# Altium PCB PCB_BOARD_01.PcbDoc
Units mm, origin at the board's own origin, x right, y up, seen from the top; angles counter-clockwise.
Board outline 110.24 x 84.07 mm, 2 copper layers (Top Layer, Bottom Layer); 80 components, 68 nets, 254 pads, 49 vias.
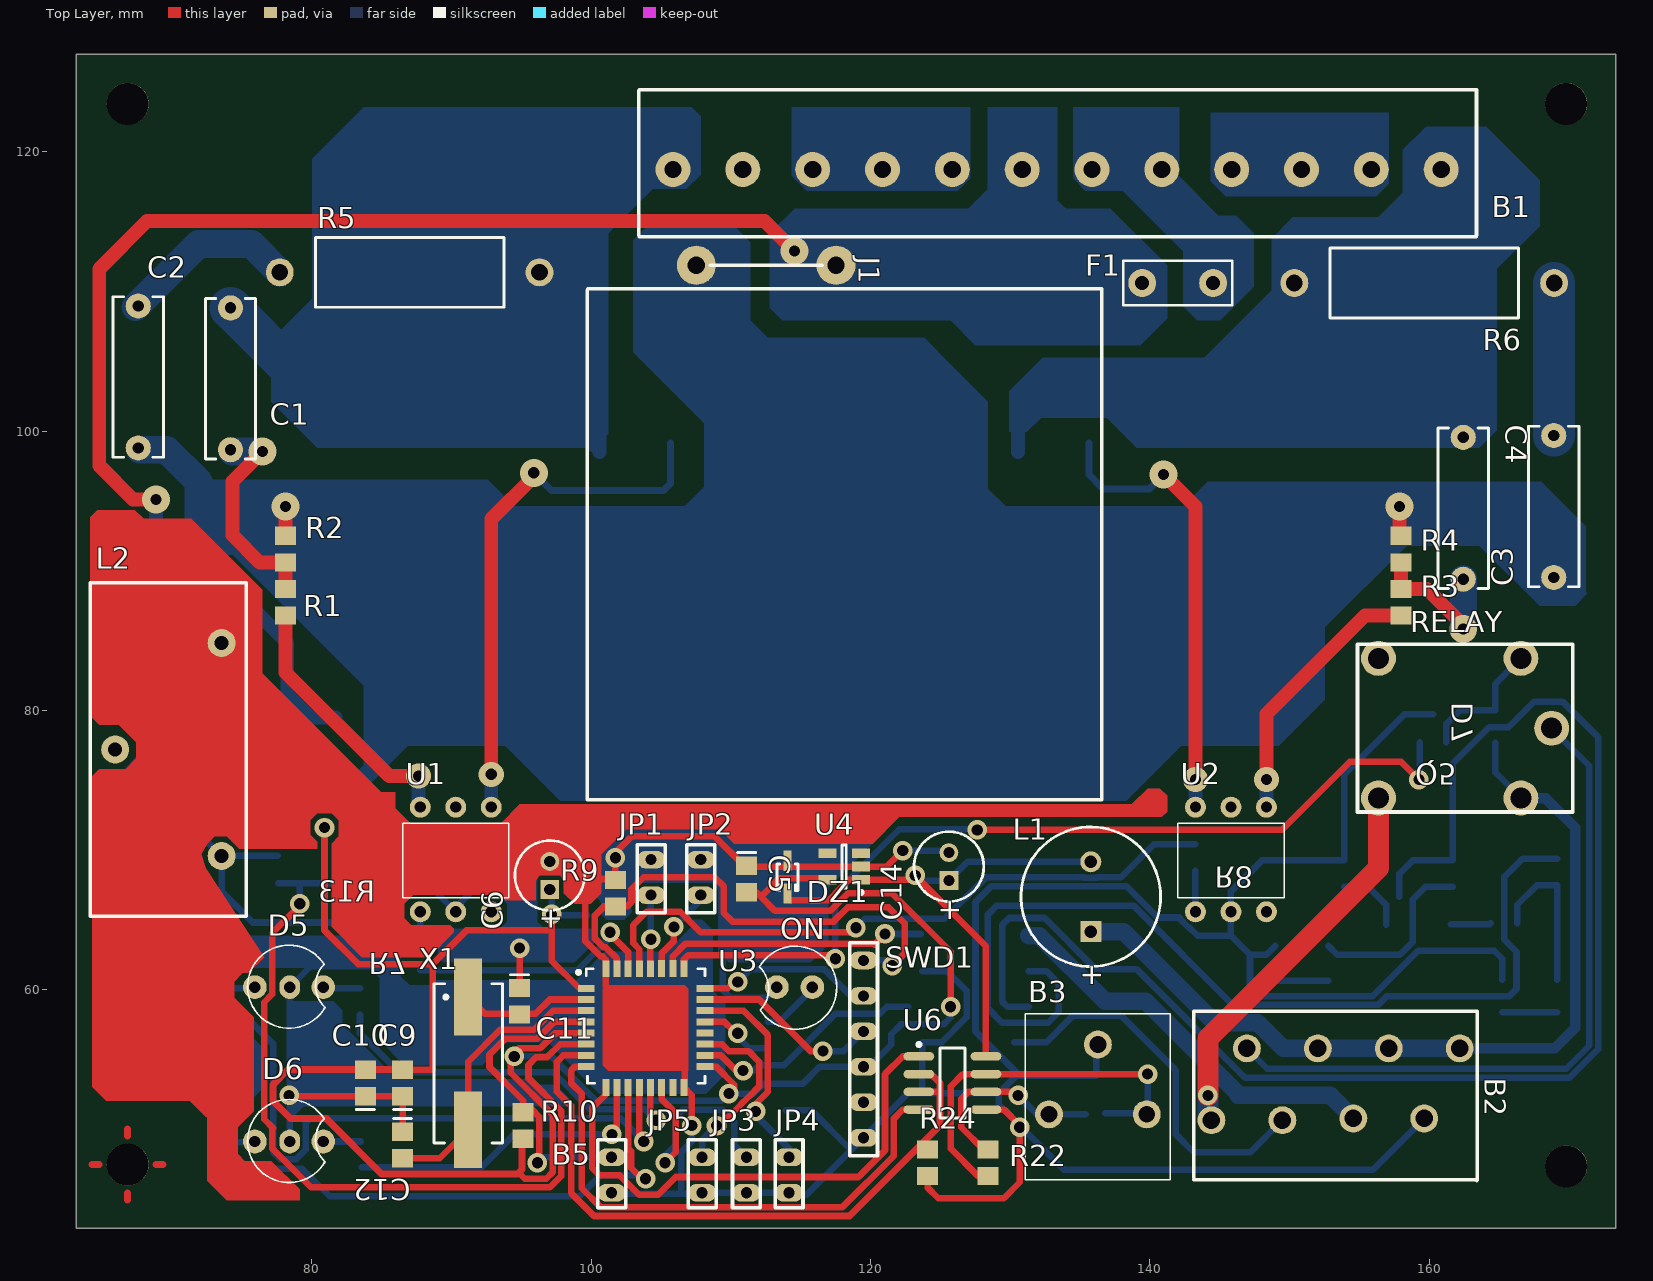
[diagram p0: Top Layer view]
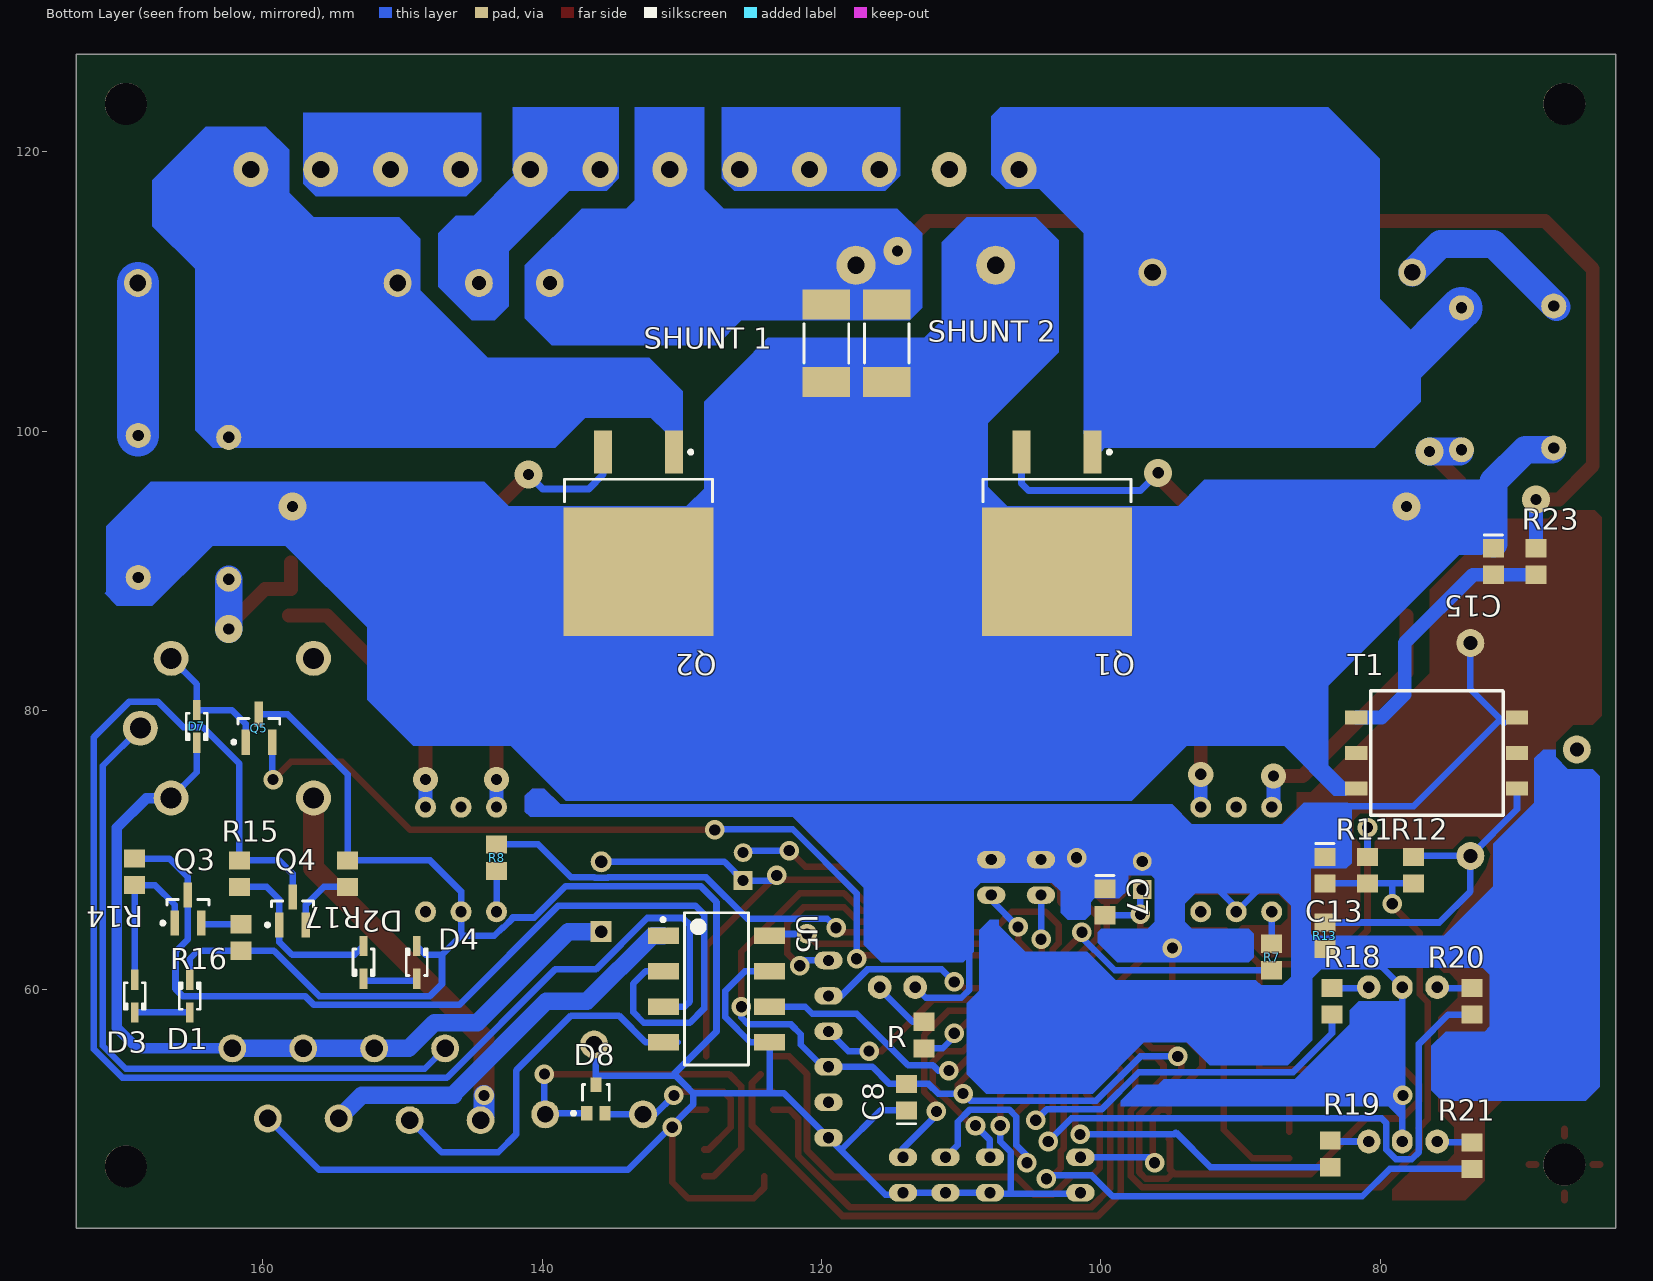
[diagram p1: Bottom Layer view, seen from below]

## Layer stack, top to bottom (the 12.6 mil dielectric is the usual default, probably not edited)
Top Solder: solder mask 0.0102, Solder Resist, Dk 3.5
Top Layer: signal copper 0.0356
Dielectric 1: dielectric 0.32, FR-4, Dk 4.8
Bottom Layer: signal copper 0.0356
Bottom Solder: solder mask 0.0102, Solder Resist, Dk 3.5

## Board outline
63.119,42.926 173.355,42.926 173.355,127 63.119,127

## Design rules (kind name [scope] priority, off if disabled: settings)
Clearance [All] p1: gap=0.152 ignorepadtopadclearanceinfootprint=FALSE except(0: Arc-Hole Track-Hole SMDPad-Hole THPad-Hole Via-Hole Fill-Hole Poly-Hole Region-Hole Text-Hole)
PolygonConnect [All] p1: connectstyle=Relief reliefconductorwidth=0.254 reliefentries=4 polygonreliefangle="90 Angle" airgapwidth=0.254
RoutingVias [All] p1: holewidth=0.711 width=1.27 viastyle="Through Hole" minholewidth=0.711 minwidth=1.27 maxholewidth=0.711 maxwidth=1.27
SolderMaskExpansion [All] p1: expansion=0.102
Width [All] p1: maxlimit=5 minlimit=0.254 preferedwidth=0.5
30 further rules are at their usual default settings.

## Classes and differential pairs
component class SPERIFERICOS: C5 C13 C14 D1 D2 D3 D4 D5 D6 D7 D8 DZ1 JP1 JP2 L1 L2 ON Q3 Q4 Q5 R R11 R12 R13 R14 R15 R16 R17 R18 R19 R20 R21 R22 R24 RELAY U4 U5 U6
component class MCU: B5 C6 C7 C8 C9 C10 C11 C12 JP3 JP4 JP5 R9 R10 SWD1 U3 X1
component class "CONTROL DE POTENCIA": B1 B2 B3 C1 C2 C3 C4 C15 F1 J1 Q1 Q2 R1 R2 R3 R4 R5 R6 R7 R8 R24 "SHUNT 1" "SHUNT 2" T1 U1 U2

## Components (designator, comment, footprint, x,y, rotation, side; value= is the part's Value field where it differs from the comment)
B1 "BLOCK TERMINAL 12P 16A" "BLOCK TERMINAL 12P 16A" 133.35,118.745 r0 top
B2 "BLOCK TERMINAL 12P 16A" "BORNERA 8P 2.5MM 2A" 153.289,53.467 r0 top
B3 "BORNERA 3P" BORNERA_ENCASTRE 136.271,53.594 r0 top
B5 "PINES_6" PINES_2_2.54 100.457,49.149 r270 top
C1 "47 nF  400V" VP60-3.6 74.168,103.759 r270 top
C2 "10nF" VP60-3.6 67.564,103.886 r270 top
C3 "10nF" VP60-3.6 168.91,94.615 r270 top
C4 "47 nF  400V" VP60-3.6 162.433,94.488 r270 top
C5 "0" 0805 111.125,67.945 r270 top
C6 "100uf 16V" CAPPR2-5X11 97.028,68.199 r90 top
C7 "10 nF" 0805 99.695,66.294 r270 bottom
C8 "1000 nF" 0805 113.919,52.324 r90 bottom
C9 "100 nF" 0805 86.487,53.34 r90 top
C10 "100nF" 0805 83.82,53.34 r90 top
C11 "10 pF" 0805 94.869,59.182 r270 top
C12 "10 pF" 0805 86.487,48.895 r270 top
C13 "10 nF" 0805 83.947,68.58 r270 bottom
C14 "100uf 16V" CAPPR2-5X11 125.603,68.834 r90 top
C15 "10 nF" 0805 71.882,90.678 r270 bottom
D1 "1N4448" SOD-323 169.164,59.563 r270 bottom
D2 "1N4448" SOD-323 152.781,61.976 r270 bottom
D3 "1N4448" SOD-323 165.227,59.563 r90 bottom
D4 "1N4448" SOD-323 148.971,61.976 r90 bottom
D5 "B1" LED_BICOLOR 78.359,60.198 r0 top
D6 "B2" LED_BICOLOR 78.359,49.149 r0 top
D7 "1N4448" SOD-323 164.719,78.867 r270 bottom
D8 "CDSOT23-SM712" SOT-323 136.144,52.197 r180 bottom
DZ1 "MM5Z5V1T1G" SOD323 114.046,68.072 r270 top
F1 "FUSE" VP45-3.2 141.986,110.617 r180 top
J1 "JUMPER" "JUMPER 10MM" 112.522,111.887 r0 top
JP1 "PINES_6" PINES_2_2.54 105.283,65.659 r90 top
JP2 "PINES_6" PINES_2_2.54 108.839,65.659 r90 top
JP3 "PINES_6" PINES_2_2.54 110.109,49.149 r270 top
JP4 "PINES_6" PINES_2_2.54 113.157,49.149 r270 top
JP5 "PINES_6" PINES_2_2.54 106.934,49.149 r270 top
L1 "1mH 200mW" CAPPR5-10X12.5 135.763,66.675 r90 top
L2 "INDUCTOR" AC1015 69.723,77.216 r270 top
ON "ON" LED 114.554,60.198 r180 top (schematic designator D)
Q1 "T2050H" TO254P1280-3_4M 103.124,92.71 r270 bottom
Q2 "T2050H" TO254P1280-3_4M 133.096,92.71 r270 bottom
Q3 "BC817" SOT23-3M 165.354,65.786 r90 bottom
Q4 "BC817" SOT23-3M 157.861,65.659 r90 bottom
Q5 "BSS138" SOT23-3M 160.274,78.74 r90 bottom
R "56 ohm" ERA-0805 112.649,56.769 r90 bottom
R1 "390" ERA-0805 78.105,87.757 r270 top (schematic designator R3)
R2 "470" ERA-0805 78.105,91.567 r270 top (schematic designator R1)
R3 "390" ERA-0805 157.988,87.757 r270 top (schematic designator R4)
R4 "470" ERA-0805 157.988,91.567 r270 top (schematic designator R2)
R5 "39 2W" R12x4 86.995,111.379 r180 top
R6 "39 2W" R12x4 159.639,110.617 r0 top
R7 "220" ERA-0805 87.757,62.357 r90 bottom
R8 "220" ERA-0805 143.256,69.469 r270 bottom
R9 "100K" ERA-0805 101.727,66.929 r270 top
R10 "10K" ERA-0805 95.123,50.292 r270 top
R11 "330" ERA-0805 80.899,68.58 r90 bottom
R12 "220" ERA-0805 77.597,68.58 r270 bottom
R13 "100" ERA-0805 83.947,63.881 r90 bottom
R14 "520" ERA-0805 169.164,68.453 r270 bottom
R15 "520" ERA-0805 161.671,68.326 r270 bottom
R16 "56 ohm" ERA-0805 161.544,63.754 r270 bottom
R17 "56 ohm" ERA-0805 153.924,68.326 r90 bottom
R18 "56 ohm" ERA-0805 83.439,59.182 r90 bottom
R19 "56 ohm" ERA-0805 83.566,48.26 r90 bottom
R20 "56 ohm" ERA-0805 73.406,59.182 r90 bottom
R21 "56 ohm" ERA-0805 73.406,48.133 r90 bottom
R22 "100" ERA-0805 128.397,47.625 r90 top
R23 "10" ERA-0805 68.834,90.678 r90 bottom
R24 "1K" ERA-0805 124.079,47.625 r90 top (schematic designator R23)
RELAY "RELE SIMPLE INVERSOR" "RELAY NT78" 162.56,78.74 r180 top
"SHUNT 1" "0,2 ohm" M1WS-2512 119.634,106.299 r270 bottom
"SHUNT 2" "0,2" M1WS-2512 115.316,106.299 r270 bottom
SWD1 "PINES_6" PINES_6_2.54 118.491,63.246 r270 top
T1 "TRANSFORMADOR" "TRANSFORMADOR TRANSMISION DE DATOS" 75.946,76.962 r0 bottom
U1 "MOC3041" DIP_6 90.297,69.342 r0 top
U2 "MOC3021" DIP_6 145.796,69.342 r0 top
U3 "STMF030K6T6" LQFP_32 103.886,57.277 r0 top
U4 "MIC5504-3.3YM5-TR" SOT23-5AM 118.11,68.834 r180 top
U5 "MCT6" S-DIP-8 127.508,60.071 r270 bottom
U6 "THVD1500" D008_N 125.857,53.34 r0 top
X1 "8Mhz Cristal" HC49/4H_SMX 91.186,54.737 r270 top

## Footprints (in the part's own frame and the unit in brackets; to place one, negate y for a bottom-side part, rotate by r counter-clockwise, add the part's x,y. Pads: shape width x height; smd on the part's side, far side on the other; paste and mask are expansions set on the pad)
0805 [mm] "Chip Capacitor; Body 2.0 x 1.2 mm (LxW typ)"
  rect 1.3x1.5 smd: 1(-0.95,0) 2(0.95,0)
  silkscreen extent -1.9,-0.65 -1.9,0.65
AC1015 [mm] "Transformador de corriente no invasivo"
  round 2 hole 1: 1(-7.62,3.81) 2(7.62,3.81) 3(0,-3.81)
  silkscreen extent -11.94,-5.59 11.94,5.59
"BLOCK TERMINAL 12P 16A" [mm] "8 pines, paso 5 mm, 16A 400V"
  round 2.5 hole 1.25: 1(-27.5,0) 2(-22.5,0) 3(-17.5,0) 4(-12.5,0) 5(-7.5,0) 6(-2.5,0) 7(2.5,0) 8(7.5,0) 9(12.5,0) 10(17.5,0) 11(22.5,0) 12(27.5,0)
  silkscreen extent -29.96,-4.83 30.03,5.7
"BORNERA 8P 2.5MM 2A" [mm]
  round 2 hole 1.25: 1(-8.89,-2.794) 2(-6.35,2.349) 3(-3.81,-2.794) 4(-1.27,2.349) 5(1.27,-2.667) 6(3.81,2.349) 7(6.35,-2.667) 8(8.89,2.349)
  silkscreen extent -10.16,-7.11 10.16,5.02
BORNERA_ENCASTRE [mm] "PASO 3.5MM 3 POLOS"
  round 2 hole 1.2: 1(-3.5,-2.5) 2(0,2.5) 3(3.5,-2.5)
  silkscreen extent -5.2,-7.2 5.2,4.7
CAPPR2-5X11 [mm] "Capacitor, Electrolytic, Radial; Body 5 x 11 mm (Dia.xH typ); Pin Spacing 2 mm (typ)"
  rect 1.35x1.35 hole 0.8: 1(-1,0)
  round 1.35 hole 0.8: 2(1,0)
  silkscreen extent -2.5,-2.5 2.5,2.5
CAPPR5-10X12.5 [mm] "Capacitor, Electrolytic, Radial; Body 10 x 12.5 mm (Dia.xH typ); Pin Spacing 5 mm (typ)"
  rect 1.5x1.5 hole 0.9: 1(-2.5,0)
  round 1.5 hole 0.9: 2(2.5,0)
  silkscreen extent -5,-5 5,5
D008_N [mm] "SOIC, 8-Leads, Body 4.9x3.9mm, Pitch 1.27mm, IPC Medium Density"
  oval 2.2x0.6 smd: 1(-2.4,1.905) 2(-2.4,0.635) 3(-2.4,-0.635) 4(-2.4,-1.905) 5(2.4,-1.905) 6(2.4,-0.635) 7(2.4,0.635) 8(2.4,1.905)
  silkscreen extent -2.52,-2.5 0.9,2.88, body extent -1.95,-2.45 1.95,2.45, height 1.75
DIP_6 [mm]
  round 1.5 hole 0.8: 1(-2.54,-3.746) 2(0,-3.746) 3(2.54,-3.746) 4(2.54,3.746) 5(0,3.746) 6(-2.54,3.746)
  silkscreen extent -3.81,-2.73 3.81,2.6
ERA-0805 [mm] "Chip Resistor; Body 2 x 1.3 mm (LxW typ)"
  rect 1.3x1.5 smd: 1(-0.95,0) 2(0.95,0)
HC49/4H_SMX [mm] "Surface Mount Quartz Crystal; Body 13.4 (inc. leads) x 4.9 mm (LxW max)"
  rect 5.5x2 smd: 1(-4.75,0) 2(4.75,0)
  silkscreen extent -5.7,-2.45 5.7,2.45
"JUMPER 10MM" [mm] "JUMPER 10MM"
  round 2.8 hole 1.25: 1(-5,0) 2(5,0)
  silkscreen extent -4,0 4,0
LED [mm] "LED 5MM"
  round 1.7 hole 0.8: 1(-1.27,0) 2(1.27,0)
  silkscreen extent -3.02,-2.93 2.52,3.01
LED_BICOLOR [mm] "LTL.30EFJ"
  round 1.7 hole 0.8: 1(2.45,0) 3(-2.45,0)
  oval 1.5x1.7 hole 0.8: 2(0.05,0)
  silkscreen extent -2.97,-2.93 2.57,3.01
LQFP_32 [mm] "LQFP, 32-Leads, Body 7x7mm, Pitch 0.8mm"
  rect 1.2x0.5 smd: 1(-4.25,2.838) 2(-4.25,2.038) 3(-4.25,1.238) 4(-4.25,0.438) 5(-4.25,-0.362) 6(-4.25,-1.162) 7(-4.25,-1.962) 8(-4.25,-2.762) 17(4.25,-2.762) 18(4.25,-1.962) 19(4.25,-1.162) 20(4.25,-0.362) 21(4.25,0.438) 22(4.25,1.238) 23(4.25,2.038) 24(4.25,2.838)
  rect 0.5x1.2 smd: 9(-2.85,-4.262) 10(-2.05,-4.262) 11(-1.25,-4.262) 12(-0.45,-4.262) 13(0.35,-4.262) 14(1.15,-4.262) 15(1.95,-4.262) 16(2.75,-4.262) 25(2.75,4.238) 26(1.95,4.263) 27(1.15,4.263) 28(0.35,4.238) 29(-0.45,4.238) 30(-1.25,4.238) 31(-2.05,4.238) 32(-2.85,4.238)
  silkscreen extent -4.92,-3.96 4.25,4.24, body extent -4.12,-3.94 4.03,4.21, height 1
M1WS-2512 [mm] "Chip Resistor; Body 6.4 x 3.2 mm (LxW typ)"
  rect 2.15x3.4 smd: 1(-2.775,0) 2(2.775,0)
  silkscreen extent -1.4,-1.6 1.4,1.6
PINES_2_2.54 [mm]
  oval 1.27x2.032 hole 0.8: 1(1.13,1) 2(3.67,1)
  silkscreen extent -0.12,0 4.75,2
PINES_6_2.54 [mm]
  oval 1.27x2.032 hole 0.8: 1(1.13,1) 2(3.67,1) 3(6.21,1) 4(8.75,1) 5(11.29,1) 6(13.83,1)
  silkscreen extent -0.12,0 15.13,2
R12x4 [mm] "Resistor, Axial; Body 13.5 x 5 mm (LxDia. max), Lead Dia. 0.85 mm (max)"
  round 2 hole 1.2: 1(-9.3,0) 2(9.3,0)
  silkscreen extent -6.75,-2.5 6.75,2.5
"RELAY NT78" [mm] "RELE SIMPLE INVERSOR"
  round 2.5 hole 1.5: 1(-4,5) 2(-4,-5) 3(-6.2,0) 4(6.2,5) 5(6.2,-5)
  silkscreen extent -7.7,-6 7.7,6
S-DIP-8 [mm] "DIP; 8 Trim Leads; Row Spacing 7.62 mm; Pitch 2.54 mm"
  rect 1.2x2.2 smd: 1(-3.81,-3.8) 2(-1.27,-3.8) 3(1.27,-3.8) 4(3.81,-3.8) 5(3.81,3.8) 6(1.27,3.8) 7(-1.27,3.8) 8(-3.81,3.8)
  silkscreen extent -5.45,-3.95 5.45,2.3
SOD323 [mm] "SOD-323/SC-76; 2 Leads; Body 1.7 x 1.3 mm, (LxW)"
  rect 1.45x0.55 smd: 1(1.175,0) 2(-1.175,0)
  silkscreen extent -0.95,-0.75 0.95,0.75
SOD-323 [mm] "SOD-323/SC-76; 2 Leads; Body 1.7 x 1.3 mm, (LxW)"
  rect 1.45x0.55 smd: 1(1.175,0) 2(-1.175,0)
  silkscreen extent -0.95,-0.75 0.95,0.75
SOT23-3M [mm] "SOT23, 3-Leads, Body 2.9x1.3mm, Pitch 0.95mm, Lead Span 2.5mm, IPC Low Density"
  rect 1.8x0.6 smd: 1(-1,0.95) 2(-1,-0.95) 3(1,0)
  silkscreen extent -1.12,-1.5 0.7,1.93, body extent -0.7,-1.5 0.7,1.5, height 1.1
SOT23-5AM [mm] "SOT23, 5-Leads, Body 2.9x1.7mm, Pitch 0.95mm, Lead Span 2.8mm, IPC Low Density"
  rect 1.3x0.7 smd: 1(-1.2,0.95) 2(-1.2,0) 3(-1.2,-0.95) 4(1.2,-0.95) 5(1.2,0.95)
  silkscreen extent -1.33,-1.55 0.15,1.97, body extent -0.9,-1.55 0.9,1.55, height 1.45
SOT-323 [mm] "SOT-323/SC-70; 3 Leads; Body 2.2 x 2.2 mm, inc. leads (LxW max)"
  rect 0.8x1.05 smd: 1(-0.65,-1.025) 2(0.65,-1.025) 3(0,1.025)
  silkscreen extent -1.73,-1.15 0.95,1.03
TO254P1280-3_4M [mm] "TO, 4-Leads, Body 9.6x10.2mm, Pitch 2.54mm, Lead Span 12.8mm, IPC Low Density"
  rect 3.1x1.3 smd: 1(-5.8,2.54) 3(-5.8,-2.54)
  rect 9.2x10.75 smd: 4(2.75,0)
  silkscreen extent -5.92,-5.3 -2.25,5.3, body extent -4.35,-5.3 5.25,5.3, height 5.1
"TRANSFORMADOR TRANSMISION DE DATOS" [mm] "TRANFORMADOR DE AUDIO PARA TRANSMISION DE DATOS SMD"
  rect 1.6x1 smd: 1(-5.75,2.54) 2(-5.75,0) 3(-5.75,-2.54) 4(5.75,-2.54) 5(5.75,0) 6(5.75,2.54)
  silkscreen extent -4.76,-4.47 4.73,4.46
VP45-3.2 [mm] "Capacitor, Ceramic, Thru-Hole, Dipped Radial; Body 7.8 x 3.2 mm (WxT) Pin Spacing 5.08 mm (typ)"
  round 2 hole 1: 1(-2.54,0) 2(2.54,0)
  silkscreen extent -3.9,-1.6 3.9,1.6
VP60-3.6 [mm] "Capacitor, Ceramic, Thru-Hole, Dipped Radial; Body 11.5 x 3.6 mm (WxT) Pin Spacing 10.16 mm (typ)"
  round 1.8 hole 0.8: 1(-5.08,0) 2(5.08,0)
  silkscreen extent -5.75,-1.8 5.75,1.8

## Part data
B5 JP1 JP2 JP3 JP4 JP5 SWD1: "6 Pines - 2.54 mm"
C1 C4 C5 C7 C8 C9 C10 C11 C12 C13 C15: library part C0805, "Ceramic Chip Capacitor - Standard"
C2 C3: library part VP52BA102GC, "Dipped Radial Multilayer Ceramic Capacitor COG (NPO): 1000pF, 200V"
C6 C14: library part 94SL106X0016CBP, "CAPACITOR ELECTROLITICO RADIAL"
D1 D2 D3 D4 D7: library part 1N4044, "275 Amp Avg Power Silicon Rectifier Diode"
D5 D6: library part LED_BICOLOR_CC, "Led bicolor catodo comun"
D8: library part BAR64-05W, "PIN Diode for RF switches (High Isolation)"
DZ1: library part 1N968B, "Half Watt Zener"
F1: "Fusible 0697H9200-02 - 20A Slow"
J1: "PUENTE"
L1: library part INDUCTOR, "INDUCTOR SMD"
L2: "INDUCTOR SMD"
ON: library part LED, "LED"
Q1 Q2: library part Q8025R5, "Triac (25.0 Amps)"
Q3 Q4: library part BC817-16LT1, "General Purpose Transistor NPN Silicon"
Q5: library part IRF5NJZ48, "HEXFET Power MOSFET"
R R1 R2 R3 R4 R7 R8 R9 R10 R11 R12 R13 R14 R15 R16 R17 R18 R19 R20 R21 R22 R23 R24 "SHUNT 1" "SHUNT 2": library part ERAS, "Metal Film Thermosensitive Chip Resistor, 0.56 Ohm to 10k Ohm Range, 5% Tolerance, 0805 Size, 0.1 W"
R5 R6: library part ERG2, "Metal Oxide Film Resistor, 0.1 Ohm to 100k Ohm Range, 2% and 5% Tolerance, 2 W"
U1: library part MOC3021, "OPTOACOPLADOR"
U2: "OPTOACOPLADOR"
U4: library part MC33275ST-5.0T3, "Low Dropout 300mA Voltage Regulator"
U5: library part PC827, "OPTOACOPLADOR"
U6: library part TL3695D, "Differential Bus Transceiver"
X1: library part HC49/4H_SMX, "Surface Mount Quartz Crystal"

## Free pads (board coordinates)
  round 3 hole 3: 2(66.802,47.498) 2(66.802,123.444) 2(169.799,47.371) 2(169.799,123.444)

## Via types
v1: diameter 1.4, hole 0.8, Top Layer to Bottom Layer, 37 vias
v2: diameter 2, hole 0.8, Top Layer to Bottom Layer, 8 vias
v3: diameter 1.8, hole 0.8, Top Layer to Bottom Layer, 4 vias

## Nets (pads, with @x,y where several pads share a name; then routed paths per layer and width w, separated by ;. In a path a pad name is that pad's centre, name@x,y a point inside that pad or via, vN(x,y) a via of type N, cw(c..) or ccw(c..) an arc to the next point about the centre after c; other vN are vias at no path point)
3V3: C5.2 C6.1 C7.2 C8.2 C9.2 C10.2 R10.2 R11.2 SWD1.4 U3.1 U3.5 U3.17 U4.5 | length 165.8
  Top Layer w0.47: v1(80.899,71.628) 80.899,64.262 83.312,61.849 88.646,61.849 ; C9.2 88.646,54.29 88.646,61.849 ; 94.982,46.736 95.236,46.482 96.774,46.482 97.226,46.934 97.226,51.086 94.234,54.079 94.234,55.245 94.801,55.812 96.325,55.812 97.428,56.915 U3.5 ; 97.028,64.262 91.059,64.262 88.646,61.849 ; 97.155,62.357 97.155,62.098 ; v1(97.155,65.405) 97.155,62.098 ; U3.1 99.138,60.115 97.155,62.098 ; U3.17 108.934,54.515 110.236,53.213 v1@110.236,52.705 ; C5.2 111.821,66.995 112.141,66.675 ; U4.5 116.91,68.009 113.475,68.009 112.141,66.675 ; v1(125.73,58.801) 125.73,62.738 121.539,66.929 118.383,66.929 117.113,65.659 113.157,65.659 112.141,66.675
  Top Layer w0.5: C9.2 C10.2 78.293,54.29 77.216,53.213 77.216,52.035 78.451,50.8 81.026,50.8 84.991,46.835 94.714,46.835 95.037,47.158 95.037,49.256 R10.2
  Bottom Layer w0.47: R11.2 v1(80.899,71.628) ; v1(94.488,55.245) 97.155,55.245 100.33,52.07 109.347,52.07 v1(109.855,52.578) 111.633,52.578 112.329,53.274 C8.2 115.123,53.274 116.345,54.496 SWD1.4 119.901,54.496 121.475,56.07 121.475,56.832 122.174,57.531 125.222,57.531 125.73,58.039 v1(125.73,58.801) ; v1(97.155,65.405) C6.1@97.155,67.072 ; v1@97.348,65.344 C7.2
5V: B2.4 B2.6 B2.8 D7.1 L1.1 RELAY.1 | length 62.3
  Bottom Layer w0.47: D7.1 164.719,75.581 RELAY.1
  Bottom Layer w0.75: B2.8 168.974,55.816 170.447,57.29 170.447,71.615 168.322,73.74 RELAY.1
  Bottom Layer w1.25: L1.1@136.017,64.175 138.136,64.175 144.653,57.658 147.701,57.658 149.542,55.816 B2.4 B2.6 B2.8
5VCC: C14.1 DZ1.1 L1.2 U4.1 U6.8 | length 38.3
  Top Layer w0.47: DZ1.1@114.046,66.421 115.715,66.421 115.763,66.373 116.279,66.373 116.327,66.421 116.995,66.421 117.947,67.374 117.947,67.393 118.439,67.884 U4.1 122.875,67.884 v1(123.19,68.199) 128.257,63.132 U6.8
  Bottom Layer w0.47: v1(123.19,68.199) 123.555,67.834 C14.1 126.944,69.175 L1.2
GND: B2.7 B3.2 B5.2 C5.1 C6.2 C7.1 C8.1 C9.1 C10.1 C11.1 C12.1 C13.1 C14.2 D3.1 D4.1 D5.2 D6.2 D8.3 DZ1.2 JP1.2 JP2.2 JP3.2 JP4.2 JP5.2 L2.1 ON.2 Q5.3 R9.1 R13.1 R16.2 R17.2 R24.1 SWD1.6 T1.3 U1.2 U2.2 U3.16 U3.32 U4.2 U5.5 U5.7 U6.5 | length 365.9
  Top Layer w0.47: v1(78.359,52.451) 78.42,52.39 C10.1 C9.1 C12.1 ; C11.1 v1(94.869,62.992) ; R9.1@101.727,67.818 R9.1 R9.1@101.727,67.945 ; R9.1@102.108,67.945 R9.1@101.727,67.945 ; U3.16 107.188,52.463 v1(107.188,50.292) ; U3.16@106.68,53.059 106.68,54.61 101.036,60.254 U3.32 101.036,62.159 100.77,62.425 100.638,62.425 99.568,63.495 99.568,66.802 100.711,67.945 R9.1@101.727,67.945 ; v1@122.555,70.231 v1(122.301,69.977) 121.158,68.834 U4.2 110.998,68.834 108.839,70.993 102.87,70.993 101.727,69.85 v1(101.727,69.469) R9.1@101.727,67.945 ; R24.1 124.079,45.847 124.841,45.085 129.54,45.085 130.683,46.228 v1(130.683,50.165) 130.683,50.292 129.54,51.435 U6.5
  Bottom Layer w0.47: 71.12,79.121 71.374,79.375 ; L2.1 73.533,81.534 71.374,79.375 ; D6.2@78.359,49.353 D6.2@78.409,49.303 ; D6.2 D6.2@78.409,49.303 ; D6.2@78.486,49.226 D6.2@78.409,49.303 ; v1(94.869,62.992) 94.869,69.072 94.996,69.199 ; C7.1 99.695,68.199 ; B5.2 101.541,45.395 107.85,45.395 JP5.2 JP3.2 JP4.2@114.03,45.479 ; 106.426,45.479 106.426,48.387 107.188,49.149 v1(107.188,50.292) ; JP2.2@107.699,69.469 v1(101.727,69.469) 100.711,69.469 99.695,68.453 99.695,68.199 ; JP2.2 108.09,69.329 109.41,68.008 109.403,68.001 109.403,60.015 109.982,59.436 112.522,59.436 ON.2 ; C8.1 115.758,51.374 118.54,48.592 ; JP4.2@114.157,45.352 115.427,45.352 SWD1.6 122.692,52.617 129.159,52.617 ; v1(122.301,69.977) 125.46,69.977 C14.2 ; 123.708,52.627 U5.5 125.095,56.261 126.873,58.039 126.873,59.944 125.476,61.341 U5.7 ; 130.549,53.982 127.508,57.023 127.508,66.294 128.651,67.437 135.012,67.437 135.034,67.415 136.492,67.415 136.514,67.437 138.303,67.437 140.553,65.187 142.111,65.187 142.119,65.18 142.119,65.124 142.785,64.458 142.841,64.458 143.418,63.881 145.796,63.881 ; B3.2@136.144,55.967 136.144,53.848 130.415,53.848 129.469,52.901 129.469,52.888 129.159,52.578 129.159,51.816 130.429,50.546 130.429,49.911 131.064,49.911 133.858,47.117 155.956,47.117 B2.7 ; D4.1 148.336,62.516 147.161,62.516 ; Q5.3 158.226,79.74 153.924,75.438 R17.2 148.016,69.276 145.796,67.056 U2.2 145.796,63.881 ; D3.1 165.227,62.23 164.653,62.804 R16.2 159.197,62.804 155.956,59.563 148.026,59.563 147.161,60.428 147.161,62.516 ; 71.374,79.375 77.597,73.152 82.296,73.152 83.947,71.501 C13.1 84.521,69.53 85.598,68.453 ; D6.2@78.409,49.303 D5.2 81.142,62.931 R13.1 84.521,62.931 85.598,64.008 85.598,68.453 ; 85.598,68.453 87.439,68.453 U1.2 90.297,65.913 93.583,69.199 94.996,69.199 ; 94.996,69.199 C6.2 98.695,69.199 99.695,68.199 ; 145.796,63.881 147.161,62.516
NetB1_1: B1.1 C1.1 Q1.1 R5.1 | length 55.3
  Bottom Layer w1: 78.486,104.521 100.457,104.521 ; Q1.1 100.584,107.09 R5.1 103.661,118.745 B1.1
  Bottom Layer w3: C1.1 78.486,104.521
NetB1_3: B1.3 B1.4 B1.5 | length 10
  Bottom Layer w1: B1.3 B1.4 B1.5
NetB1_6: "SHUNT 1.1" "SHUNT 2.1" B1.6 F1.2 J1.2 R23.2 | length 107
  Top Layer w1: v2(68.834,95.123) 67.183,95.123 64.77,97.536 64.77,111.633 68.199,115.062 112.395,115.062 v2(114.554,112.903)
  Bottom Layer w1: R23.2 v2(68.834,95.123) ; 117.475,109.074 117.475,111.84 117.428,111.887 120.396,111.887 123.952,115.443 127.548,115.443 128.905,116.8 ; B1.6 128.905,116.8 ; F1.2 136.271,113.792 131.913,113.792 128.905,116.8
NetB1_7: B1.7 B1.8 F1.1 | length 14.7
  Bottom Layer w1: B1.7 B1.8 141.478,118.117 141.478,117.221 144.526,114.173 F1.1
NetB1_9: B1.9 B1.10 B1.11 | length 10
  Bottom Layer w1: B1.9 B1.10 B1.11
NetB1_12: B1.12 C4.1 Q2.1 R6.1 | length 41.8
  Bottom Layer w1: Q2.1 130.556,100.076 131.953,101.473 141.986,101.473 150.339,109.826 R6.1 155.448,110.617 161.036,116.205 161.036,118.559 B1.12
NetB2_1: B2.1 RELAY.4 | length 28.2
  Top Layer w1.5: v1(144.145,52.451) 144.145,56.515 156.36,68.73 RELAY.4
  Bottom Layer w1.5: v1(144.145,52.451) 144.145,50.927 B2.1
NetB2_2: B2.2 RELAY.3 | length 49.6
  Bottom Layer w0.47: B2.2 148.399,54.356 169.799,54.356 171.45,56.007 171.45,76.05 RELAY.3
NetB2_3: B2.3 U5.4 | length 27.7
  Bottom Layer w0.47: U5.4@130.292,56.261 132.588,56.261 134.493,58.166 137.922,58.166 141.859,54.229 141.859,49.657 143.129,48.387 147.193,48.387 B2.3
NetB2_5: B2.5 U5.1 | length 28.6
  Bottom Layer w1.25: U5.1 132.08,63.881 136.783,59.178 139.704,59.178 146.304,52.578 ; 146.304,52.451 152.908,52.451 B2.5
NetB3_1: B3.1 D8.2 R22.2 U6.6 | length 13.9
  Top Layer w0.47: R22.2 128.082,48.575 126.492,50.165 126.492,52.197 127,52.705 U6.6 v1@130.175,52.705
  Bottom Layer w0.47: v1(130.556,52.451) 131.913,51.094 B3.1 D8.2@135.416,51.094
NetB3_3: B3.3 D8.1 R22.1 U6.7 | length 28.1
  Top Layer w0.47: R22.1 127.696,46.675 125.73,48.641 125.73,53.086 126.619,53.975 U6.7 v1(139.827,53.975)
  Bottom Layer w0.47: D8.1 B3.3@139.693,51.172 ; B3.3@139.827,51.15 v1(139.827,53.975)
NetB5_1: B5.1 R10.1 U3.4 | length 23.5
  Top Layer w0.47: v1@96.139,47.371 v1(96.139,47.625) ; v1@96.266,47.625 96.266,50.927 95.758,51.435 95.316,51.435 R10.1 95.123,52.07 92.71,54.483 92.71,55.372 93.853,56.515 96.139,56.515 97.339,57.715 U3.4
  Bottom Layer w0.47: v1(96.139,47.625) 96.533,48.019 B5.1
NetC1_2: C1.2 R1.1 R2.2 | length 15.6
  Top Layer w1: v2(76.454,98.552) 74.295,96.393 74.295,92.583 76.261,90.617 R2.2 R1.1
  Bottom Layer w2: C1.2@74.295,98.552 v2(76.454,98.552)
NetC2_1: C2.1 R5.2 | length 13.2
  Top Layer w1: R5.2@77.597,111.281 R5.2
  Bottom Layer w2: C2.1@67.373,108.902 71.882,113.411 75.663,113.411 R5.2
NetC2_2: "SHUNT 1.2" "SHUNT 2.2" C2.2 C3.2 C15.1 J1.1 Q1.4 Q2.4 R2.1 R4.1 T1.6 | length 88
  Top Layer w1: R2.1 v2(78.105,94.615) ; v2(157.861,94.615) 157.861,92.644 R4.1
  Bottom Layer w1: 72.837,91.628 117.348,91.628 117.475,91.755 117.475,103.524 ; J1.1 107.522,108.251 112.249,103.524 115.316,103.524 117.475,103.524 ; 119.634,103.524 117.475,103.524
  Bottom Layer w2: C2.2@67.691,98.679 69.596,98.679 71.882,96.393 C15.1@71.882,91.948
NetC3_1: C3.1 R6.2 | length 10.9
  Bottom Layer w3: C3.1@168.939,99.695 R6.2
NetC4_2: C4.2 R3.1 R4.2 | length 11.2
  Top Layer w1: R4.2 R3.1 159.832,88.707 162.433,86.106 v2(162.433,85.852)
  Bottom Layer w2: v2(162.433,85.852) C4.2
NetC11_2: C11.2 U3.2 X1.1 | length 9.4
  Top Layer w0.47: X1.1 92.38,58.293 96.012,58.293 97.034,59.315 U3.2
NetC12_2: C12.2 U3.3 X1.2 | length 20.4
  Top Layer w0.47: C12.2 89.144,47.945 X1.2 91.186,54.864 93.472,57.15 95.894,57.15 97.258,58.515 U3.3
NetC13_2: C13.2 R11.1 R12.2 U3.6 | length 62.1
  Top Layer w0.47: v1@78.994,65.913 77.146,64.065 77.146,59.685 76.579,59.118 76.579,50.744 77.216,50.107 77.172,50.062 77.172,48.636 79.948,45.86 97.032,45.86 97.849,46.677 97.849,51.344 95.504,53.689 95.504,54.628 96.066,55.189 96.845,55.189 97.771,56.115 U3.6
  Bottom Layer w0.47: R12.2 C13.2 ; v1(79.121,66.167) 79.121,67.503
NetC15_2: C15.2 R23.1 T1.4 | length 19.3
  Bottom Layer w1: R23.1 C15.2 73.34,89.728 78.232,84.836 78.232,81.153 79.883,79.502 T1.4
NetD1_1: D1.2 Q3.1 R14.2 | length 11.5
  Bottom Layer w0.47: Q3.1 166.304,66.101 167.706,67.503 R14.2 D1.2
NetD1_2: D1.1 D3.2 | length 3.9
  Bottom Layer w0.47: D3.2 D1.1
NetD2_1: D2.2 Q4.1 R15.2 | length 13
  Bottom Layer w0.47: D2.2 153.416,62.516 157.893,62.516 158.811,63.434 Q4.1 158.811,66.482 159.705,67.376 R15.2
NetD2_2: D2.1 D4.2 | length 3.8
  Bottom Layer w0.47: D4.2@148.971,60.674 D2.1@152.781,60.674
NetD5_1: D5.1 R18.2 | length 2.6
  Bottom Layer w0.47: D5.1@80.875,60.132 R18.2
NetD5_3: D5.3 R20.2 | length 2.4
  Bottom Layer w0.47: R20.2 D5.3@75.843,60.132
NetD6_1: D6.1 R19.2 | length 2.7
  Bottom Layer w0.47: D6.1 R19.2@83.505,49.149
NetD6_3: D6.3 R21.2 | length 2.5
  Bottom Layer w0.47: R21.2 75.843,49.083 D6.3
NetD7_1: D7.2 Q5.1 RELAY.2 | length 9.7
  Bottom Layer w0.47: Q5.1 161.224,79.055 162.211,80.042 D7.2 164.719,81.899 RELAY.2
NetD_1: ON.1 R.2 | length 4.3
  Bottom Layer w0.47: R.2 113.472,57.719 115.824,60.071 ON.1
NetJP1_1: JP1.1 U3.28 | length 5.5
  Top Layer w0.47: U3.28 v1@104.236,63.881
  Bottom Layer w0.47: v1(104.267,63.627) JP1.1@104.267,66.773
NetJP2_1: JP2.1 U3.27 | length 6.4
  Top Layer w0.47: U3.27 105.036,62.618 105.918,63.5 v1(105.918,64.516)
  Bottom Layer w0.47: v1(105.918,64.516) 107.823,66.421 JP2.1@107.823,66.773
NetJP3_1: JP3.1 U3.14 | length 17.4
  Top Layer w0.47: U3.14 105.036,52.19 106.045,51.181 106.045,48.387 v1(105.283,47.625)
  Bottom Layer w0.47: v1(105.283,47.625) 105.283,48.133 106.045,48.895 106.045,50.927 106.553,51.435 109.361,51.435 110.236,50.56 110.236,48.892 JP3.1
NetJP4_1: JP4.1 U3.22 | length 14.8
  Top Layer w0.47: U3.22 110.903,58.515 112.649,56.769 112.649,52.705 v1@111.887,51.943
  Bottom Layer w0.47: v1(111.76,51.308) 111.76,51.054 114.157,48.657 JP4.1@114.157,47.892
NetJP5_1: JP5.1 U3.19 | length 13.1
  Top Layer w0.47: U3.19 109.358,56.115 109.846,55.626 111.252,55.626 112.014,54.864 112.014,53.086 111.323,52.395 111.31,52.395 110.673,51.758 110.673,51.745 109.22,50.292 v1(108.966,50.292)
  Bottom Layer w0.47: JP5.1 107.934,49.26 v1(108.966,50.292)
NetL2_2: L2.2 R12.1 R13.2 T1.1 | length 24.1
  Bottom Layer w0.47: T1.1 70.196,72.933 L2.2 ; R12.1@77.531,69.596 L2.2 ; R13.2 75.758,64.831 73.533,67.056 L2.2
NetQ1_3: Q1.3 U1.4 | length 39
  Top Layer w1: v3@92.837,75.057 v3(92.837,75.438) 92.837,93.726 95.885,96.774 v2(95.885,97.028)
  Bottom Layer w0.5: v2(95.885,97.028) 97.155,95.758 105.156,95.758 105.664,96.266 Q1.3@105.664,99.145
  Bottom Layer w1: U1.4 v3(92.837,75.438)
NetQ2_3: Q2.3 U2.6 | length 33.3
  Top Layer w1: v2(140.97,96.901) 143.256,94.615 v3(143.256,75.057) v3@143.256,74.93
  Bottom Layer w0.5: Q2.3@135.636,99.145 135.636,96.901 136.652,95.885 139.954,95.885 v2(140.97,96.901)
  Bottom Layer w1: U2.6 v3(143.256,75.057)
NetQ3_2: Q3.2 R16.1 | length 2.9
  Bottom Layer w0.47: R16.1 164.322,64.704 Q3.2
NetQ3_3: Q3.3 R14.1 U5.2 | length 71.4
  Bottom Layer w0.47: U5.2 132.588,61.341 133.477,60.452 133.477,58.42 132.715,57.658 129.413,57.658 128.397,58.674 128.397,65.405 129.032,66.04 138.82,66.04 145.932,58.928 156.337,58.928 156.972,59.563 165.735,59.563 166.243,60.071 166.243,62.738 165.354,63.627 Q3.3 165.354,68.072 166.685,69.403 R14.1
NetQ4_2: Q4.2 R17.1 | length 5
  Bottom Layer w0.47: R17.1 155.636,67.376 156.911,66.101 Q4.2
NetQ4_3: Q4.3 R15.1 U5.3 | length 104.4
  Bottom Layer w0.47: U5.3 129.794,58.801 129.413,59.182 129.413,64.643 129.921,65.151 132.461,65.151 136.144,61.468 139.065,61.468 146.812,53.721 170.044,53.721 172.085,55.762 172.085,78.105 169.545,80.645 167.513,80.645 165.672,78.804 164.284,78.804 161.671,76.192 R15.1 158.811,69.276 157.861,68.326 Q4.3
NetQ5_2: Q5.2 U3.25 | length 65.3
  Top Layer w0.47: U3.25 106.636,62.186 106.934,62.484 117.221,62.484 v1(117.475,62.23) ; v1(127.635,71.456) 149.434,71.456 154.305,76.327 157.988,76.327 v1(159.258,75.057)
  Bottom Layer w0.47: v1(117.475,62.23) 117.475,66.929 122.047,71.501 v1@127.635,71.501 ; v1@159.324,75.123 Q5.2
NetR1_2: R1.2 U1.6 | length 18.8
  Top Layer w1: R1.2 78.105,82.74 85.534,75.311 v3(87.63,75.311)
  Bottom Layer w1: U1.6@87.63,73.215 v3(87.63,75.311)
NetR3_2: R3.2 U2.4 | length 19.5
  Top Layer w1: v3@148.336,74.93 v3(148.336,75.057) 148.336,79.756 155.387,86.807 R3.2@158.115,86.807
  Bottom Layer w1: U2.4 v3(148.336,75.057)
NetR7_1: R7.1 U3.30 | length 18.3
  Top Layer w0.47: v1(101.346,64.135) 101.346,64.008 102.636,62.718 U3.30
  Bottom Layer w0.47: R7.1 98.999,61.407 v1@101.727,64.135
NetR7_2: R7.2 U1.1 | length 2.3
  Bottom Layer w0.47: R7.2 U1.1
NetR8_1: R8.1 U3.29 | length 47.2
  Top Layer w0.47: U3.29 103.436,62.92 102.997,63.359 102.997,64.643 103.957,65.603 106.368,65.603 107.005,64.966 107.005,64.953 107.823,64.135 118.618,64.135 v1(118.941,64.458)
  Bottom Layer w0.47: v1(118.941,64.458) 119.578,65.095 125.293,65.095 128.257,68.059 135.27,68.059 135.292,68.038 136.234,68.038 136.256,68.059 137.909,68.059 140.269,70.419 R8.1
NetR8_2: R8.2 U2.1 | length 2.9
  Bottom Layer w0.47: U2.1 R8.2
NetR9_2: R9.2 SWD1.1 U3.31 | length 37.4
  Top Layer w0.47: U3.31@101.854,61.533 U3.31 101.836,62.248 101.036,63.048 100.896,63.048 100.259,63.685 100.259,65.334 100.904,65.979 R9.2 102.555,65.979 102.88,66.304 102.88,67.212 103.479,67.811 103.498,67.811 103.759,68.072 108.839,68.072 109.474,67.437 109.474,65.532 110.109,64.897 117.348,64.897 118.364,65.913 121.285,65.913 122.428,64.77 122.428,62.611 v1(121.552,61.735)
  Bottom Layer w0.47: SWD1.1 121.171,62.116 v1(121.552,61.735)
NetR18_1: R18.1 U3.13 | length 27.6
  Top Layer w0.47: U3.13 104.236,51.085 v1(104.648,50.673)
  Bottom Layer w0.47: R18.1 83.439,56.896 86.233,54.102 97.282,54.102 99.936,51.448 103.873,51.448 v1(104.648,50.673)
NetR19_1: R19.1 U3.10 | length 22.5
  Top Layer w0.47: v1(101.473,49.657) 101.836,50.02 U3.10
  Bottom Layer w0.47: R19.1 92.141,47.31 94.615,49.784 94.742,49.657 v1(101.473,49.657)
NetR20_1: R20.1 U3.12 | length 46.2
  Top Layer w0.47: U3.12 103.436,49.472 v1(103.759,49.149)
  Bottom Layer w0.47: R20.1 75.118,58.232 77.216,56.134 77.216,48.387 77.724,47.879 78.867,47.879 79.546,48.558 79.546,50.463 79.883,50.8 102.108,50.8 v1(103.759,49.149)
NetR21_1: R21.1 U3.11 | length 38.6
  Top Layer w0.47: U3.11 102.636,48.667 102.86,48.442 102.86,47.254 v1@103.632,46.482
  Bottom Layer w0.47: R21.1 79.309,47.183 81.267,45.225 99.148,45.225 100.659,46.736 v1@103.632,46.736
  other v1: 103.886,46.482
NetR23_2: R24.2 U3.7 U6.2 U6.3 | length 47.3
  Top Layer w0.47: U3.7 97.987,55.315 97.536,54.864 97.536,52.705 98.552,51.689 98.552,45.466 100.203,43.815 118.491,43.815 124.968,50.292 124.968,52.705 ; U6.3 124.968,52.705 ; U6.2@124.333,53.975 124.968,53.34 124.968,52.705
NetR_1: R.1 U3.21 | length 5
  Top Layer w0.47: U3.21 109.544,57.715 v1@110.109,57.15
  Bottom Layer w0.47: v1(110.49,56.896) 110.49,56.642 111.313,55.819 R.1
NetSWD1_2: SWD1.2 U3.24 | length 12.2
  Top Layer w0.47: U3.24 109.772,60.115 v1@110.045,60.389
  Bottom Layer w0.47: v1(110.49,60.579) 111.379,61.468 116.699,61.468 118.591,59.576 SWD1.2
NetSWD1_3: SWD1.3 U3.23 | length 13.5
  Top Layer w0.47: U3.23 112.008,59.315 115.697,55.626 v1(116.586,55.626)
  Bottom Layer w0.47: v1(116.586,55.626) 118.081,55.626 SWD1.3
NetU3_8: U3.8 U6.4 | length 39.1
  Top Layer w0.47: U3.8 98.838,54.515 98.552,54.229 98.552,53.34 99.314,52.578 99.314,45.795 100.659,44.45 117.983,44.45 121.666,48.133 121.666,50.8 122.301,51.435 U6.4
NetU3_9: U3.9 U6.1 | length 37.7
  Top Layer w0.47: U3.9 101.036,52.522 100.528,52.014 100.515,52.014 100.054,51.553 100.054,47.266 100.584,46.736 102.027,46.736 103.424,45.339 104.775,45.339 106.045,46.609 119.126,46.609 121.031,48.514 121.031,53.975 122.301,55.245 U6.1
NetU3_18: U3.18 U5.6 | length 16.4
  Top Layer w0.47: U3.18 109.277,55.315 v1@110.363,54.229
  Bottom Layer w0.47: v1(110.871,54.229) 111.633,54.229 112.014,54.61 113.792,54.61 117.475,58.293 120.65,58.293 121.158,58.801 U5.6@122.692,58.801
NetU3_26: U3.26 U5.8 | length 19.3
  Top Layer w0.47: U3.26 105.836,62.402 106.751,63.317 120.269,63.317 ; 120.269,63.246 v1(121.031,64.008)
  Bottom Layer w0.47: v1(121.031,64.008) U5.8@123.581,64.008
pads on no net: B1.2 L2.3 RELAY.5 SWD1.5 T1.2 T1.5 U1.3 U1.5 U2.3 U2.5 U3.15 U3.20 U4.3 U4.4
copper on no net: | length 2
  Top Layer w0.5: 64.262,47.498 64.77,47.498 ; 66.802,44.958 66.802,45.466 ; 66.802,49.53 66.802,50.038 ; 68.834,47.498 69.342,47.498

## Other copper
Top Layer:
  region net GND: 101.219,54.229 100.838,54.61 100.838,60.071 100.853,60.071 101.107,60.325 106.68,60.325 106.934,60.071 106.934,54.229
  region net GND: 98.806,66.167 98.044,66.929 98.044,67.818 97.79,68.199 96.266,68.199 96.012,67.818 96.012,66.421 93.853,66.421 93.472,66.802 87.249,66.802 86.614,66.167 86.614,65.151 87.122,64.643 89.916,64.643 90.17,64.389 90.17,64.135 88.392,62.357 83.566,62.357 81.407,64.516 81.407,70.485 81.915,70.993 81.915,72.136 81.407,72.644 80.391,72.644 79.883,72.136 79.883,71.12 80.391,70.612 80.391,70.104 74.803,70.104 73.914,70.993 73.025,70.993 72.517,70.485 72.08,69.723 72.39,68.707 76.581,62.357 75.438,61.214 75.057,61.214 74.422,60.579 74.422,59.436 75.819,58.039 75.819,51.308 74.676,50.165 74.676,48.26 75.184,47.752 77.089,47.752 79.121,45.72 79.121,44.958 73.914,44.958 72.517,46.355 72.517,50.927 72.39,50.927 71.247,52.07 65.278,52.07 64.262,53.086 64.262,75.311 64.77,75.819 66.675,75.819 67.437,76.581 67.437,77.724 66.167,78.994 64.77,78.994 64.135,79.629 64.135,93.853 64.643,94.361 67.31,94.361 67.945,93.726 71.374,93.726 76.454,88.646 76.454,82.677 84.963,74.168 85.979,74.168 85.979,73.025 87.122,71.882 93.472,71.882 94.869,73.279 138.684,73.279 139.827,74.422 140.716,74.422 141.224,73.914 141.224,72.771 140.843,72.39 122.047,72.39 120.142,70.485 110.236,70.485 109.22,71.501 102.489,71.501 100.711,69.723 100.711,66.929 99.949,66.167
Bottom Layer:
  region net NetC2_2: 72.771,96.52 92.583,96.52 94.742,94.361 93.853,93.472 72.009,93.472
  region net NetB1_1: 101.219,99.809 101.219,114.173 104.394,117.348 106.807,117.348 107.823,118.364 107.823,122.555 107.188,123.19 83.693,123.19 80.01,119.507 80.01,109.474 77.089,106.553 77.089,102.108 80.391,98.806 99.695,98.806 99.949,98.552 100.076,98.552
  region net NetC2_2: 152.4,85.852 158.369,91.821 163.576,91.821 167.894,87.503 170.434,87.503 171.323,88.392 171.196,88.519 171.196,93.218 168.021,96.393 144.145,96.393 141.986,94.234 141.986,85.852
  region net NetB1_3: 115.443,117.221 126.238,117.221 127.127,118.11 127.127,123.19 114.364,123.19 114.364,118.3
  region net NetB1_6: 128.397,117.348 128.397,123.19 133.35,123.19 133.35,116.078 133.477,115.951
  region net NetB1_7: 134.493,123.19 134.493,118.11 135.382,117.221 138.049,117.221 142.367,112.903 142.367,108.966 143.383,107.95 145.034,107.95 147.447,110.363 147.447,114.173 146.177,115.443 144.907,115.443 141.986,118.364 142.113,118.491 142.113,123.19
  region net NetB1_12: 129.921,99.949 129.921,102.87 132.334,105.283 143.891,105.283 148.717,110.109 148.717,113.792 150.241,115.316 156.337,115.316 158.115,117.094 158.115,120.142 159.766,121.793 164.084,121.793 167.894,117.983 167.894,114.681 164.846,111.633 164.846,100.076 163.576,98.806 139.065,98.806 136.906,100.965 132.207,100.965 131.191,99.949
  region net NetB1_6: 113.665,107.95 112.776,108.839 112.776,114.173 114.554,115.951 127,115.951 130.429,119.38 131.826,119.38 131.826,118.11 133.985,115.951 137.16,115.951 141.224,111.887 141.224,108.077 139.319,106.172 127.508,106.172 125.73,107.95
  region net NetC2_2: 128.397,102.108 128.397,95.885 129.667,94.615 129.413,94.361 104.521,94.361 104.648,94.488 106.553,94.488 108.077,96.012 108.077,100.584 105.791,102.87 102.997,105.664 102.997,113.665 104.648,115.316 109.601,115.316 111.379,113.538 111.379,107.95 112.649,106.68 123.825,106.68 125.857,104.648
  region net NetC2_2: 74.295,91.186 83.693,81.788 83.693,76.073 82.423,74.803 82.423,73.914 83.312,73.914 86.868,77.47 93.853,77.47 97.79,73.533 138.303,73.533 142.24,77.47 149.225,77.47 152.527,80.772 152.527,94.615 148.844,94.615 72.771,94.615 71.755,93.599 71.755,91.186
  region net GND: 78.409,50.673 79.375,51.639 79.375,51.689 98.552,51.689 98.552,52.07 97.409,53.213 95.885,53.213 95.504,53.594 86.106,53.594 82.169,57.531 82.169,58.547 81.534,59.182 78.409,59.182
  region net GND: 79.883,61.468 84.201,61.468 84.836,60.833 84.836,56.388 86.614,54.61 92.202,54.61 93.853,56.261 96.901,56.261 100.584,52.578 108.204,52.578 109.601,53.975 109.601,59.055 108.712,59.944 108.712,64.262 107.95,65.024 107.315,65.024 107.315,64.643 105.41,62.738 100.965,62.738 98.933,60.706 88.9,60.706 88.519,60.325 86.995,60.325 86.36,60.96 86.36,66.04 87.249,66.929 93.218,66.929 93.98,66.167 93.98,64.897 93.472,64.389 89.408,64.389 89.027,64.008 89.027,62.357 89.408,61.976 98.806,61.976 100.203,63.373 100.203,64.135 99.949,64.389 96.647,64.389 96.139,64.897 96.139,67.945 96.393,68.199 98.044,68.199 98.044,67.183 98.679,66.548 100.457,66.548 100.711,66.294 100.711,65.405 101.092,65.024 102.362,65.024 102.87,65.532 102.87,67.056 103.505,67.691 108.585,67.691 109.093,67.183 109.093,62.738 109.855,61.976 115.697,61.976 116.967,63.246 116.967,67.31 122.047,72.39 140.843,72.39 141.224,72.771 141.224,73.914 140.716,74.422 139.827,74.422 138.684,73.279 94.869,73.279 93.472,71.882 86.995,71.882 85.471,73.406 82.296,73.406 82.042,73.152 82.042,69.088 82.423,68.707 84.963,68.707 84.963,64.008 84.836,63.881 75.438,63.881 71.882,67.437 71.882,70.485 68.961,73.406 68.961,76.581 68.326,77.216 67.437,77.216 67.437,76.708 66.548,75.819 64.77,75.819 64.262,75.311 64.262,53.086 65.278,52.07 75.565,52.07 76.327,52.832 76.327,56.007 75.311,57.023 72.517,57.023 72.136,57.404 72.136,61.087 72.644,61.595 79.806,61.595
  region net NetB1_9: 145.415,116.84 156.21,116.84 157.099,117.729 157.099,122.809 144.335,122.809 144.335,117.919

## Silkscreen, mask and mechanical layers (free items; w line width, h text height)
Top Overlay:
  lines w0.254: 99.695,110.109 99.695,73.619 136.555,73.619 136.555,110.219 99.755,110.219
Bottom Paste:
  region: 128.27,123.19 128.397,123.063 128.397,117.348 127,115.951 114.554,115.951 114.554,115.824 112.776,114.046 112.776,108.839 113.792,107.823 113.919,107.95 125.73,107.95 127.508,106.172 139.319,106.172 141.351,108.204 141.351,111.887 137.287,115.951 133.985,115.951 133.35,116.586 133.35,123.19
  region: 134.493,123.19 134.493,118.11 135.382,117.221 138.049,117.221 142.367,112.903 142.367,108.966 143.383,107.95 145.034,107.95 147.447,110.363 147.447,114.3 147.32,114.3 146.177,115.443 144.907,115.443 141.986,118.364 142.113,118.491 142.113,123.19
  region: 144.272,122.809 144.272,117.983 145.415,116.84 156.21,116.84 157.099,117.729 157.099,122.809
  region: 114.272,123.19 114.272,117.983 115.415,116.84 126.21,116.84 127.099,117.729 127.099,123.19
Mechanical 1:
  lines w0.254: 63.246,43.434 63.246,127 ; 63.246,43.612 63.246,43.053 173.355,43.053 173.355,127 63.322,127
